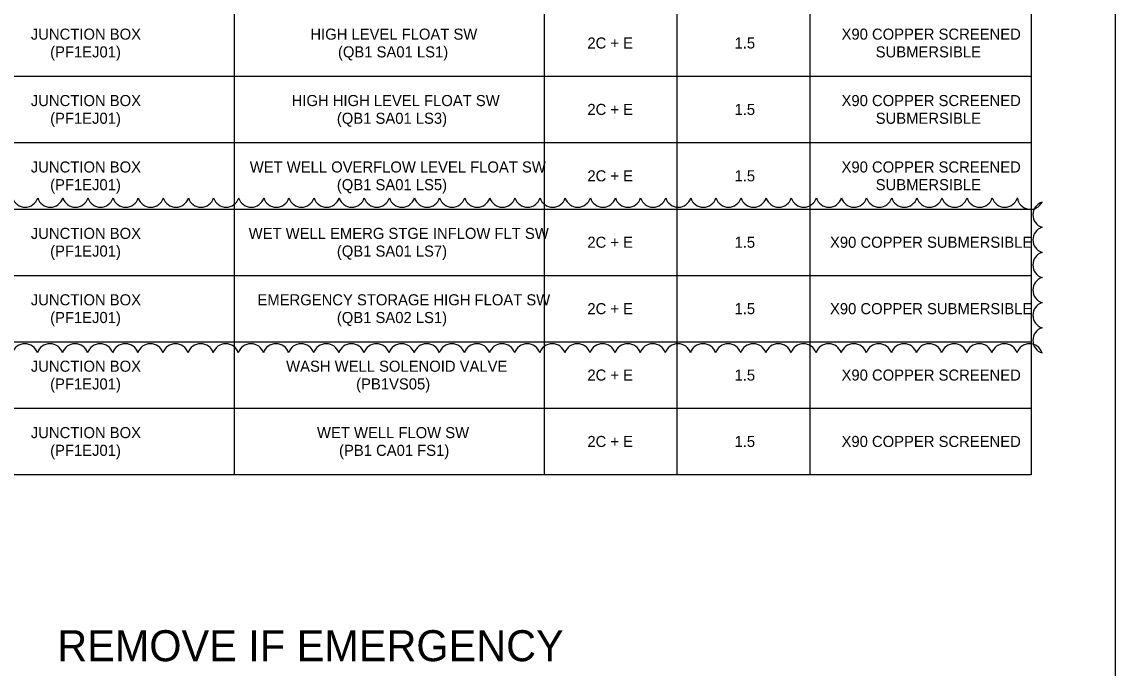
# Model space of a CAD drawing. Extents: x 0 to 841, y 0 to 594.
# Drawn here: x 582 to 829, y 146.3 to 292.3 of the extents above; entities that cross this region are included whole.
import ezdxf

# ---------------------------------------------------------------- set-up
doc = ezdxf.new("R2010")
doc.units = 0
for name, color, linetype in [('A1BORDER', 7, 'Continuous'), ('INSTALLED', 7, 'Continuous'), ('Level 1', 7, 'Continuous')]:
    doc.layers.add(name, color=color, linetype=linetype)

msp = doc.modelspace()

# ---------------------------------------------------------------- linework, layer by layer
at = {"layer": 'A1BORDER'}
msp.add_line((829, 581), (829, 15), dxfattribs=at)
at = {"layer": 'INSTALLED'}
for p, q in [((630, 560), (630, 190)), ((700, 560), (700, 190)), ((730, 560), (730, 190)), ((760, 560), (760, 190)), ((520, 280), (810, 280)), ((520, 265), (810, 265)), ((520, 250), (810, 250)), ((520, 235), (810, 235)), ((520, 220), (810, 220)), ((520, 205), (810, 205))]:
    msp.add_line(p, q, dxfattribs=at)
msp.add_lwpolyline([(520, 560), (810, 560), (810, 190), (520, 190)], close=True, dxfattribs=at)
at = {"layer": 'Level 1'}
for centre, radius, start, end in [((582.76, 253.39), 2.98, 197.5, 342.5), ((588.43, 253.39), 2.98, 197.5, 342.5), ((594.11, 253.39), 2.98, 197.5, 342.5), ((599.78, 253.39), 2.98, 197.5, 342.5), ((605.46, 253.39), 2.98, 197.5, 342.5), ((611.13, 253.39), 2.98, 197.5, 342.5), ((616.81, 253.39), 2.98, 197.5, 342.5), ((622.48, 253.39), 2.98, 197.5, 342.5), ((628.16, 253.39), 2.98, 197.5, 342.5), ((633.83, 253.39), 2.98, 197.5, 342.5), ((639.5, 253.39), 2.98, 197.5, 342.5), ((645.18, 253.39), 2.98, 197.5, 342.5), ((650.85, 253.39), 2.98, 197.5, 342.5), ((656.53, 253.39), 2.98, 197.5, 342.5), ((662.2, 253.39), 2.98, 197.5, 342.5), ((667.88, 253.39), 2.98, 197.5, 342.5), ((673.55, 253.39), 2.98, 197.5, 342.5), ((679.23, 253.39), 2.98, 197.5, 342.5), ((684.9, 253.39), 2.98, 197.5, 342.5), ((690.58, 253.39), 2.98, 197.5, 342.5), ((696.25, 253.39), 2.98, 197.5, 342.5), ((701.93, 253.39), 2.98, 197.5, 342.5), ((707.6, 253.39), 2.98, 197.5, 342.5), ((713.28, 253.39), 2.98, 197.5, 342.5), ((718.95, 253.39), 2.98, 197.5, 342.5), ((724.62, 253.39), 2.98, 197.5, 342.5), ((730.3, 253.39), 2.98, 197.5, 342.5), ((735.97, 253.39), 2.98, 197.5, 342.5), ((741.65, 253.39), 2.98, 197.5, 342.5), ((747.32, 253.39), 2.98, 197.5, 342.5), ((753, 253.39), 2.98, 197.5, 342.5), ((758.67, 253.39), 2.98, 197.5, 342.5), ((764.35, 253.39), 2.98, 197.5, 342.5), ((770.02, 253.39), 2.98, 197.5, 342.5), ((775.7, 253.39), 2.98, 197.5, 342.5), ((781.37, 253.39), 2.98, 197.5, 342.5), ((787.05, 253.39), 2.98, 197.5, 342.5), ((792.72, 253.39), 2.98, 197.5, 342.5), ((798.39, 253.39), 2.98, 197.5, 342.5), ((804.07, 253.39), 2.98, 197.5, 342.5), ((809.85, 252.91), 2.97, 187.8392, 332.8392), ((813.39, 248.71), 2.98, 107.5, 252.5), ((813.39, 243.04), 2.98, 107.5, 252.5), ((813.39, 237.36), 2.98, 107.5, 252.5), ((813.39, 231.69), 2.98, 107.5, 252.5), ((813.39, 226.01), 2.98, 107.5, 252.5), ((813.39, 220.34), 2.98, 107.5, 252.5), ((582.68, 216.61), 2.98, 17.5, 162.5), ((588.35, 216.61), 2.98, 17.5, 162.5), ((594.03, 216.61), 2.98, 17.5, 162.5), ((599.7, 216.61), 2.98, 17.5, 162.5), ((605.38, 216.61), 2.98, 17.5, 162.5), ((611.05, 216.61), 2.98, 17.5, 162.5), ((616.72, 216.61), 2.98, 17.5, 162.5), ((622.4, 216.61), 2.98, 17.5, 162.5), ((628.07, 216.61), 2.98, 17.5, 162.5), ((633.75, 216.61), 2.98, 17.5, 162.5), ((639.42, 216.61), 2.98, 17.5, 162.5), ((645.1, 216.61), 2.98, 17.5, 162.5), ((650.77, 216.61), 2.98, 17.5, 162.5), ((656.45, 216.61), 2.98, 17.5, 162.5), ((662.12, 216.61), 2.98, 17.5, 162.5), ((667.8, 216.61), 2.98, 17.5, 162.5), ((673.47, 216.61), 2.98, 17.5, 162.5), ((679.15, 216.61), 2.98, 17.5, 162.5), ((684.82, 216.61), 2.98, 17.5, 162.5), ((690.5, 216.61), 2.98, 17.5, 162.5), ((696.17, 216.61), 2.98, 17.5, 162.5), ((701.84, 216.61), 2.98, 17.5, 162.5), ((707.52, 216.61), 2.98, 17.5, 162.5), ((713.19, 216.61), 2.98, 17.5, 162.5), ((718.87, 216.61), 2.98, 17.5, 162.5), ((724.54, 216.61), 2.98, 17.5, 162.5), ((730.22, 216.61), 2.98, 17.5, 162.5), ((735.89, 216.61), 2.98, 17.5, 162.5), ((741.57, 216.61), 2.98, 17.5, 162.5), ((747.24, 216.61), 2.98, 17.5, 162.5), ((752.92, 216.61), 2.98, 17.5, 162.5), ((758.59, 216.61), 2.98, 17.5, 162.5), ((764.27, 216.61), 2.98, 17.5, 162.5), ((769.94, 216.61), 2.98, 17.5, 162.5), ((775.61, 216.61), 2.98, 17.5, 162.5), ((781.29, 216.61), 2.98, 17.5, 162.5), ((786.96, 216.61), 2.98, 17.5, 162.5), ((792.64, 216.61), 2.98, 17.5, 162.5), ((798.31, 216.61), 2.98, 17.5, 162.5), ((803.99, 216.61), 2.98, 17.5, 162.5), ((809.66, 216.61), 2.98, 17.5, 162.5)]:
    msp.add_arc(centre, radius, start, end, dxfattribs=at)

# ---------------------------------------------------------------- texts
at = {"layer": 'INSTALLED'}
for s, p in [('JUNCTION BOX', (584.04, 288.25)), ('HIGH LEVEL FLOAT SW', (647.19, 288.25)), ('X90 COPPER SCREENED', (767.19, 288.25)), ('(PF1EJ01)', (588.4, 284.25)), ('(QB1 SA01 LS1)', (653.42, 284.25)), ('2C + E', (709.77, 286.25)), ('1.5', (743.01, 286.25)), ('SUBMERSIBLE', (774.91, 284.25)), ('JUNCTION BOX', (584.04, 273.25)), ('HIGH HIGH LEVEL FLOAT SW', (642.96, 273.25)), ('X90 COPPER SCREENED', (767.19, 273.25)), ('(PF1EJ01)', (588.4, 269.25)), ('(QB1 SA01 LS3)', (653.17, 269.25)), ('2C + E', (709.77, 271.25)), ('1.5', (743.01, 271.25)), ('SUBMERSIBLE', (774.91, 269.25)), ('JUNCTION BOX', (584.04, 258.25)), ('WET WELL OVERFLOW LEVEL FLOAT SW', (633.5, 258.25)), ('X90 COPPER SCREENED', (767.19, 258.25)), ('(PF1EJ01)', (588.4, 254.25)), ('(QB1 SA01 LS5)', (653.17, 254.25)), ('2C + E', (709.77, 256.25)), ('1.5', (743.01, 256.25)), ('SUBMERSIBLE', (774.91, 254.25)), ('JUNCTION BOX', (584.04, 243.25)), ('WET WELL EMERG STGE INFLOW FLT SW', (633.25, 243.25)), ('2C + E', (709.77, 241.25)), ('1.5', (743.01, 241.25)), ('X90 COPPER SUBMERSIBLE', (764.58, 241.25)), ('(PF1EJ01)', (588.4, 239.25)), ('(QB1 SA01 LS7)', (653.17, 239.25)), ('JUNCTION BOX', (584.04, 228.25)), ('EMERGENCY STORAGE HIGH FLOAT SW', (635.24, 228.25)), ('2C + E', (709.77, 226.25)), ('1.5', (743.01, 226.25)), ('X90 COPPER SUBMERSIBLE', (764.58, 226.25)), ('(PF1EJ01)', (588.4, 224.25)), ('(QB1 SA02 LS1)', (653.17, 224.25)), ('JUNCTION BOX', (584.04, 213.25)), ('WASH WELL SOLENOID VALVE', (641.72, 213.25)), ('2C + E', (709.77, 211.25)), ('1.5', (743.01, 211.25)), ('X90 COPPER SCREENED', (767.19, 211.25)), ('(PF1EJ01)', (588.4, 209.25)), ('(PB1VS05)', (657.53, 209.25)), ('JUNCTION BOX', (584.04, 198.25)), ('WET WELL FLOW SW', (648.69, 198.25)), ('2C + E', (709.77, 196.25)), ('1.5', (743.01, 196.25)), ('X90 COPPER SCREENED', (767.19, 196.25)), ('(PF1EJ01)', (588.4, 194.25)), ('(PB1 CA01 FS1)', (653.67, 194.25))]:
    msp.add_text(s, height=2.5, dxfattribs=at).set_placement(p)
at = {"layer": 'Level 1'}
msp.add_text('REMOVE IF EMERGENCY', height=7, rotation=360, dxfattribs=at).set_placement((590, 147.87))

doc.saveas('drawing.dxf')
